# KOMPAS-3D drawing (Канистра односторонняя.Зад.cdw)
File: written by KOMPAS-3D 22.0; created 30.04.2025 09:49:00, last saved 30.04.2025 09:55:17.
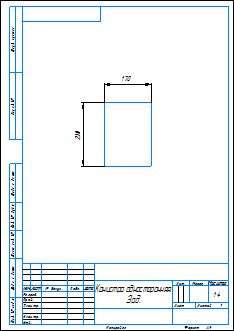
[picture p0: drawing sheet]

Sheet 1: A4, portrait

Document properties: Автор: Admin; Наименование: Канистра односторонняя. Зад

Title block, sheet 1: Наименование: Канистра односторонняя. / Зад.; scale: 1:4; Количество листов документа: 1; Форматы листов документа: A4; stored path: D:\28.11.2016\3D модели\Абилимпикс\2025\Канистра односторонняя\Канистра односторонняя.Зад.cdw

Dimensions and other numbers on the sheet: 230; 170; 1:4; 1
